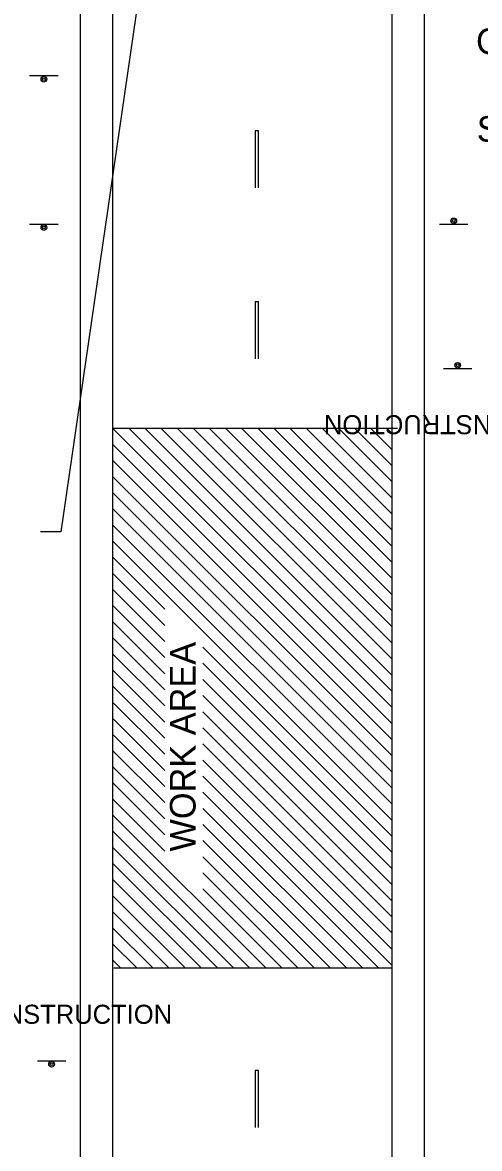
# Model space of a CAD drawing. Extents: x 1372 to 1588, y 125 to 404.
# Drawn here: x 1437.4 to 1476.2, y 229.9 to 325.5 of the extents above; entities that cross this region are included whole.
import ezdxf

# ---------------------------------------------------------------- set-up
doc = ezdxf.new("R2010")
doc.units = 0
for name, color, linetype in [('Level 10', 7, 'Continuous'), ('Level 2', 7, 'Continuous'), ('Level 44', 7, 'Continuous'), ('Level 5', 7, 'Continuous')]:
    doc.layers.add(name, color=color, linetype=linetype)

msp = doc.modelspace()

# ---------------------------------------------------------------- linework, layer by layer
at = {"layer": 'Level 10'}
for p, q in [((1445.052, 372.627), (1445.052, 157.871)), ((1468.761, 372.627), (1468.761, 157.871)), ((1471.506, 372.627), (1471.506, 202.793)), ((1442.325, 157.871), (1442.325, 334.977)), ((1445.052, 291.109), (1469.245, 291.109)), ((1445.052, 291.109), (1468.761, 267.399)), ((1446.421, 291.109), (1468.761, 268.767)), ((1447.789, 291.109), (1468.761, 270.136)), ((1449.158, 291.109), (1468.761, 271.505)), ((1450.527, 291.109), (1468.761, 272.873)), ((1451.895, 291.109), (1468.761, 274.242)), ((1453.263, 291.109), (1468.761, 275.61)), ((1454.631, 291.109), (1468.761, 276.978)), ((1456.001, 291.109), (1468.761, 278.348)), ((1457.369, 291.109), (1468.761, 279.716)), ((1458.737, 291.109), (1468.761, 281.085)), ((1460.106, 291.109), (1468.761, 282.454)), ((1461.474, 291.109), (1468.761, 283.822)), ((1462.843, 291.109), (1468.761, 285.191)), ((1464.212, 291.109), (1468.761, 286.56)), ((1465.58, 291.109), (1468.761, 287.928)), ((1466.948, 291.109), (1468.761, 289.296)), ((1468.318, 291.109), (1468.761, 290.665)), ((1445.052, 289.741), (1468.761, 266.031)), ((1445.052, 288.371), (1468.761, 264.663)), ((1445.052, 287.002), (1468.761, 263.293)), ((1445.052, 285.634), (1468.761, 261.925)), ((1445.052, 284.265), (1468.761, 260.557)), ((1445.052, 282.897), (1468.761, 259.188)), ((1445.052, 281.526), (1468.761, 257.82)), ((1445.052, 280.16), (1449.49, 275.721)), ((1445.052, 278.791), (1449.49, 274.353)), ((1445.052, 277.423), (1449.49, 272.985)), ((1445.052, 276.054), (1449.49, 271.617)), ((1445.052, 274.685), (1449.49, 270.247)), ((1445.052, 273.317), (1449.49, 268.879)), ((1452.713, 272.498), (1468.761, 256.451)), ((1445.052, 271.948), (1449.49, 267.51)), ((1445.052, 270.58), (1449.49, 266.142)), ((1452.713, 271.129), (1468.761, 255.082)), ((1452.713, 269.76), (1468.761, 253.713)), ((1445.052, 269.212), (1449.49, 264.774)), ((1445.052, 267.842), (1445.059, 267.834)), ((1445.052, 267.842), (1449.49, 263.404)), ((1452.713, 268.392), (1468.761, 252.344)), ((1452.713, 267.023), (1468.761, 250.975)), ((1445.052, 266.474), (1449.49, 262.036)), ((1445.052, 265.106), (1449.49, 260.668)), ((1452.713, 265.654), (1468.761, 249.607)), ((1452.713, 264.286), (1468.761, 248.238)), ((1445.052, 263.737), (1449.49, 259.3)), ((1452.713, 262.918), (1468.761, 246.87)), ((1445.052, 262.369), (1449.49, 257.93)), ((1452.713, 261.55), (1468.761, 245.502)), ((1445.052, 261), (1449.49, 256.562)), ((1452.713, 260.18), (1467.658, 245.235)), ((1445.052, 259.631), (1449.49, 255.192)), ((1445.052, 258.262), (1458.079, 245.235)), ((1452.713, 258.812), (1466.29, 245.235)), ((1452.713, 257.444), (1464.922, 245.235)), ((1445.052, 256.894), (1456.711, 245.235)), ((1445.052, 255.522), (1455.342, 245.235)), ((1452.713, 256.075), (1463.554, 245.235)), ((1452.713, 254.707), (1462.186, 245.235)), ((1445.052, 254.158), (1453.974, 245.235)), ((1445.052, 252.788), (1452.605, 245.235)), ((1452.713, 253.338), (1460.817, 245.235)), ((1452.713, 251.969), (1459.448, 245.235)), ((1445.052, 251.42), (1451.237, 245.235)), ((1445.052, 250.051), (1449.868, 245.235)), ((1445.052, 248.682), (1448.499, 245.235)), ((1445.052, 247.313), (1447.13, 245.235)), ((1445.052, 245.945), (1445.738, 245.259)), ((1445.164, 245.259), (1468.761, 245.259))]:
    msp.add_line(p, q, dxfattribs=at)
at = {"layer": 'Level 2'}
for p, q in [((1457.149, 316.331), (1457.149, 311.493)), ((1457.439, 316.331), (1457.149, 316.331)), ((1457.439, 311.493), (1457.439, 316.331)), ((1457.149, 301.817), (1457.149, 296.979)), ((1457.439, 301.817), (1457.149, 301.817)), ((1457.439, 296.979), (1457.439, 301.817)), ((1457.149, 236.548), (1457.149, 231.71)), ((1457.439, 236.548), (1457.149, 236.548)), ((1457.439, 231.71), (1457.439, 236.548))]:
    msp.add_line(p, q, dxfattribs=at)
at = {"layer": 'Level 44'}
for p, q in [((1440.44, 321.001), (1438.02, 321.001)), ((1440.44, 308.4), (1438.02, 308.4)), ((1472.79, 308.422), (1475.208, 308.422)), ((1473.124, 296.162), (1475.544, 296.162)), ((1441.096, 237.358), (1438.678, 237.358))]:
    msp.add_line(p, q, dxfattribs=at)
for centre, radius in [((1439.225, 320.73), 0.242), ((1439.225, 320.73), 0.121), ((1474.004, 308.694), 0.242), ((1474.004, 308.694), 0.121), ((1439.226, 308.129), 0.242), ((1439.226, 308.129), 0.121), ((1474.338, 296.433), 0.242), ((1474.338, 296.433), 0.121), ((1439.882, 237.087), 0.242), ((1439.882, 237.087), 0.121)]:
    msp.add_circle(centre, radius, dxfattribs=at)
at = {"layer": 'Level 5'}
for p, q in [((1451.707, 358.434), (1440.673, 282.299)), ((1440.673, 282.299), (1438.934, 282.299))]:
    msp.add_line(p, q, dxfattribs=at)

# ---------------------------------------------------------------- texts
at = {"layer": 'Level 10'}
for s, height, rotation, p in [('GAZETTED', 2.1774, 360, (1475.895, 322.862)), ('SPEED', 2.1774, 360, (1475.96, 315.412)), ('WORK AREA', 2.178, 90, (1452.097, 255.15))]:
    msp.add_text(s, height=height, rotation=rotation, dxfattribs=at).set_placement(p)
at = {"layer": 'Level 44'}
for rotation, p in [(179.99999, (1480.44, 292.201)), (359.99999, (1432.656, 240.519))]:
    msp.add_text('CONSTRUCTION', height=1.62, rotation=rotation, dxfattribs=at).set_placement(p)

doc.saveas('drawing.dxf')
